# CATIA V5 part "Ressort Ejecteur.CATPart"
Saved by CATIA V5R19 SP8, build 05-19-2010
Part number: Ressort éjecteur
Bounding box of the stored display mesh (mm): x -1.297 to 1.297, y -1.3 to 1.3, z -0.3 to 14.79
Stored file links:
  C:\Users\Arthur\Desktop\Catia parts\GLOCK\Ensemble culasse\Ressort Ejecteur.CATPart
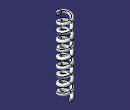
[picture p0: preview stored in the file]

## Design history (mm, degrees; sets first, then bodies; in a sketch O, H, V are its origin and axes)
Set1
  Sketch1 on yz-plane, origin (0, 0, 0), H (0, 1, 0), V (0, 0, 1)
    point P1 (1, 0)
    distance P1 V = 1
  Helix1: Direction Sketch1.V, RefPoint Sketch1, Pitch 1.5, Height 14.5, TaperAngle 0
  Plane1: type OffsetPt, RefPlane yz-plane, RefPoint Sketch1
  Circle1: type CtrRad, Start 0, End 180, Center Sketch1, Support Plane1, Radius 0.3, FirstDirection (0, 1, 0)
Body1 (main body)
  Rib1: profile Circle1, centre curve Helix1
  Plane2: type Offset, RefPlane xy-plane, Offset 0.3, reversed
